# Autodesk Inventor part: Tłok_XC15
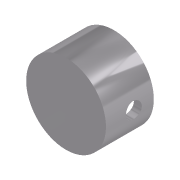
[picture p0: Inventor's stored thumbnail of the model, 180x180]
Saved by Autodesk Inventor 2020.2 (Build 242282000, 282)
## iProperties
Created: 2000-05
Part Number: Tłok_XC15
Document SubType Name: Modeling
Designer: F.Stasiak
Stock Number: Tłok_XC15
Density: 1 g/cm^3
Material: Default
Appearance: Aluminium (polerowane)
Manager: www.cadconsulting.pl
Company: Fabian Stasiak CAD Consulting
Control State: 0
Master: False
Checked Out: False
Shininess: 0.0
Density: 0.0
Volumn: 0.0
Area: 0.0
PropertySet Name: Model Information
Author: F.Stasiak
Subject: Zbiór ćwiczeń. Autodesk Inventor 2020. Kurs podstawowy
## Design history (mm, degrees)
node "Base1"
node "Bryła1"
node "Korpusy bryłowe"
node "Korpusy powierzchniowe"
